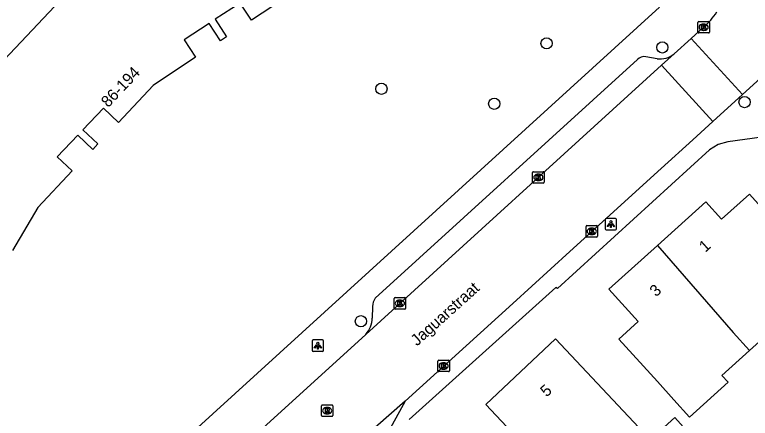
# Model space of a CAD drawing. Extents: x 163150 to 163546, y 380933 to 381635.
# Drawn here: x 163213 to 163277.1, y 381253.2 to 381288.4 of the extents above; entities that cross this region are included whole.
import ezdxf

# ---------------------------------------------------------------- set-up
doc = ezdxf.new("R2010")
doc.units = 0
for name, color, linetype in [('IMGEO_Boom', 7, 'Continuous'), ('IMGEO_Kolk', 7, 'Continuous'), ('IMGEO_Lichtpunt', 7, 'Continuous'), ('IMGEO_Openbare_ruimte_label', 7, 'Continuous'), ('IMGEO_Pand', 7, 'Continuous'), ('IMGEO_Pand_nummerreeks', 7, 'Continuous'), ('IMGEO_Rijbaan_lokaal_open', 7, 'Continuous'), ('IMGEO_Rioolput', 7, 'Continuous'), ('IMGEO_Voetpad_open', 7, 'Continuous')]:
    doc.layers.add(name, color=color, linetype=linetype)

msp = doc.modelspace()

# ---------------------------------------------------------------- linework, layer by layer
at = {"layer": 'IMGEO_Boom'}
for centre in [(163259.341, 381285.869), (163269.438, 381285.511), (163244.945, 381281.901), (163254.778, 381280.597), (163276.605, 381280.745), (163243.161, 381261.625)]:
    msp.add_circle(centre, 0.489, dxfattribs=at)
at = {"layer": 'IMGEO_Kolk'}
for p, q in [((163272.537, 381286.848), (163272.537, 381287.7)), ((163272.612, 381287.774), (163273.464, 381287.774)), ((163273.025, 381287.554), (163273.05, 381287.554)), ((163273.538, 381287.7), (163273.538, 381286.848)), ((163273.048, 381286.994), (163273.023, 381286.994)), ((163273.464, 381286.774), (163272.612, 381286.774)), ((163258.203, 381274.673), (163259.055, 381274.673)), ((163258.128, 381273.747), (163258.128, 381274.599)), ((163258.616, 381274.453), (163258.641, 381274.453)), ((163259.129, 381274.599), (163259.129, 381273.747)), ((163259.055, 381273.673), (163258.203, 381273.673)), ((163258.639, 381273.893), (163258.614, 381273.893)), ((163262.784, 381269.041), (163262.784, 381269.893)), ((163262.859, 381269.967), (163263.711, 381269.967)), ((163263.272, 381269.747), (163263.297, 381269.747)), ((163263.785, 381269.893), (163263.785, 381269.041)), ((163263.711, 381268.967), (163262.859, 381268.967)), ((163263.295, 381269.187), (163263.27, 381269.187)), ((163246.059, 381262.764), (163246.059, 381263.616)), ((163246.134, 381263.69), (163246.986, 381263.69)), ((163246.547, 381263.47), (163246.572, 381263.47)), ((163247.06, 381263.616), (163247.06, 381262.764)), ((163246.986, 381262.69), (163246.134, 381262.69)), ((163246.57, 381262.91), (163246.545, 381262.91)), ((163249.871, 381257.302), (163249.871, 381258.154)), ((163249.946, 381258.228), (163250.798, 381258.228)), ((163250.359, 381258.008), (163250.384, 381258.008)), ((163250.872, 381258.154), (163250.872, 381257.302)), ((163250.382, 381257.448), (163250.357, 381257.448)), ((163250.798, 381257.228), (163249.946, 381257.228))]:
    msp.add_line(p, q, dxfattribs=at)
for points in [[(163272.537, 381286.848), (163272.537, 381287.7)], [(163272.612, 381287.774), (163273.464, 381287.774)], [(163273.538, 381287.7), (163273.538, 381286.848)], [(163272.858, 381287.474), (163272.981, 381287.474), (163272.981, 381287.323), (163273.111, 381287.474), (163273.275, 381287.474), (163273.129, 381287.323), (163273.282, 381287.074), (163273.13, 381287.074), (163273.045, 381287.238), (163272.981, 381287.171), (163272.981, 381287.074), (163272.858, 381287.074), (163272.858, 381287.474)], [(163273.464, 381286.774), (163272.612, 381286.774)], [(163258.203, 381274.673), (163259.055, 381274.673)], [(163258.128, 381273.747), (163258.128, 381274.599)], [(163258.449, 381274.373), (163258.572, 381274.373), (163258.572, 381274.222), (163258.702, 381274.373), (163258.866, 381274.373), (163258.72, 381274.222), (163258.873, 381273.973), (163258.721, 381273.973), (163258.636, 381274.137), (163258.572, 381274.07), (163258.572, 381273.973), (163258.449, 381273.973), (163258.449, 381274.373)], [(163259.129, 381274.599), (163259.129, 381273.747)], [(163259.055, 381273.673), (163258.203, 381273.673)], [(163262.784, 381269.041), (163262.784, 381269.893)], [(163262.859, 381269.967), (163263.711, 381269.967)], [(163263.105, 381269.667), (163263.228, 381269.667), (163263.228, 381269.516), (163263.358, 381269.667), (163263.522, 381269.667), (163263.376, 381269.516), (163263.529, 381269.267), (163263.377, 381269.267), (163263.292, 381269.431), (163263.228, 381269.364), (163263.228, 381269.267), (163263.105, 381269.267), (163263.105, 381269.667)], [(163263.785, 381269.893), (163263.785, 381269.041)], [(163263.711, 381268.967), (163262.859, 381268.967)], [(163246.059, 381262.764), (163246.059, 381263.616)], [(163246.134, 381263.69), (163246.986, 381263.69)], [(163246.38, 381263.39), (163246.503, 381263.39), (163246.503, 381263.239), (163246.633, 381263.39), (163246.797, 381263.39), (163246.651, 381263.239), (163246.804, 381262.99), (163246.652, 381262.99), (163246.567, 381263.154), (163246.503, 381263.087), (163246.503, 381262.99), (163246.38, 381262.99), (163246.38, 381263.39)], [(163247.06, 381263.616), (163247.06, 381262.764)], [(163246.986, 381262.69), (163246.134, 381262.69)], [(163249.871, 381257.302), (163249.871, 381258.154)], [(163249.946, 381258.228), (163250.798, 381258.228)], [(163250.872, 381258.154), (163250.872, 381257.302)], [(163250.192, 381257.928), (163250.315, 381257.928), (163250.315, 381257.777), (163250.445, 381257.928), (163250.609, 381257.928), (163250.463, 381257.777), (163250.616, 381257.528), (163250.464, 381257.528), (163250.379, 381257.692), (163250.315, 381257.625), (163250.315, 381257.528), (163250.192, 381257.528), (163250.192, 381257.928)], [(163250.798, 381257.228), (163249.946, 381257.228)]]:
    msp.add_lwpolyline(points, dxfattribs=at)
for centre, start, end in [((163272.614, 381287.698), 91.55205, 178.44795), ((163272.614, 381287.698), 91.55205, 178.44795), ((163273.462, 381287.698), 1.55205, 88.44795), ((163273.462, 381287.698), 1.55205, 88.44795), ((163272.614, 381286.85), 181.55205, 268.44795), ((163272.614, 381286.85), 181.55205, 268.44795), ((163273.462, 381286.85), 271.55205, 358.44795), ((163273.462, 381286.85), 271.55205, 358.44795), ((163258.205, 381274.597), 91.55205, 178.44795), ((163258.205, 381274.597), 91.55205, 178.44795), ((163259.053, 381274.597), 1.55205, 88.44795), ((163259.053, 381274.597), 1.55205, 88.44795), ((163258.205, 381273.749), 181.55205, 268.44795), ((163258.205, 381273.749), 181.55205, 268.44795), ((163259.053, 381273.749), 271.55205, 358.44795), ((163259.053, 381273.749), 271.55205, 358.44795), ((163262.861, 381269.891), 91.55205, 178.44795), ((163262.861, 381269.891), 91.55205, 178.44795), ((163263.709, 381269.891), 1.55205, 88.44795), ((163263.709, 381269.891), 1.55205, 88.44795), ((163262.861, 381269.043), 181.55205, 268.44795), ((163262.861, 381269.043), 181.55205, 268.44795), ((163263.709, 381269.043), 271.55205, 358.44795), ((163263.709, 381269.043), 271.55205, 358.44795), ((163246.136, 381263.614), 91.55205, 178.44795), ((163246.136, 381263.614), 91.55205, 178.44795), ((163246.984, 381263.614), 1.55205, 88.44795), ((163246.984, 381263.614), 1.55205, 88.44795), ((163246.136, 381262.766), 181.55205, 268.44795), ((163246.136, 381262.766), 181.55205, 268.44795), ((163246.984, 381262.766), 271.55205, 358.44795), ((163246.984, 381262.766), 271.55205, 358.44795), ((163249.948, 381258.152), 91.55205, 178.44795), ((163249.948, 381258.152), 91.55205, 178.44795), ((163250.796, 381258.152), 1.55205, 88.44795), ((163250.796, 381258.152), 1.55205, 88.44795), ((163249.948, 381257.304), 181.55205, 268.44795), ((163249.948, 381257.304), 181.55205, 268.44795), ((163250.796, 381257.304), 271.55205, 358.44795), ((163250.796, 381257.304), 271.55205, 358.44795)]:
    msp.add_arc(centre, 0.0765, start, end, dxfattribs=at)
for centre, major_axis, ratio, start_param, end_param in [((163273.024, 381287.274), (-0.387, 0.002), 0.722429, 4.712389, 7.853982), ((163273.049, 381287.274), (-0.39, 0.002), 0.717154, 1.570796, 4.712389), ((163258.615, 381274.173), (-0.387, 0.002), 0.722429, 4.712389, 7.853982), ((163258.64, 381274.173), (-0.39, 0.002), 0.717154, 1.570796, 4.712389), ((163263.271, 381269.467), (-0.387, 0.002), 0.722429, 4.712389, 7.853982), ((163263.296, 381269.467), (-0.39, 0.002), 0.717154, 1.570796, 4.712389), ((163246.546, 381263.19), (-0.387, 0.002), 0.722429, 4.712389, 7.853982), ((163246.571, 381263.19), (-0.39, 0.002), 0.717154, 1.570796, 4.712389), ((163250.358, 381257.728), (-0.387, 0.002), 0.722429, 4.712389, 7.853982), ((163250.383, 381257.728), (-0.39, 0.002), 0.717154, 1.570796, 4.712389)]:
    msp.add_ellipse(centre, major_axis=major_axis, ratio=ratio, start_param=start_param, end_param=end_param, dxfattribs=at)
at = {"layer": 'IMGEO_Lichtpunt'}
for p, q in [((163264.452, 381270.502), (163264.452, 381269.695)), ((163264.452, 381270.502), (163264.452, 381269.695)), ((163265.354, 381270.597), (163264.546, 381270.597)), ((163265.354, 381270.597), (163264.546, 381270.597)), ((163265.448, 381269.695), (163265.448, 381270.502)), ((163265.448, 381269.695), (163265.448, 381270.502)), ((163264.546, 381269.601), (163265.354, 381269.601)), ((163264.546, 381269.601), (163265.354, 381269.601)), ((163239.804, 381259.997), (163238.996, 381259.997)), ((163239.804, 381259.997), (163238.996, 381259.997)), ((163238.902, 381259.902), (163238.902, 381259.095)), ((163238.902, 381259.902), (163238.902, 381259.095)), ((163239.898, 381259.095), (163239.898, 381259.902)), ((163239.898, 381259.095), (163239.898, 381259.902)), ((163238.996, 381259.001), (163239.804, 381259.001)), ((163238.996, 381259.001), (163239.804, 381259.001))]:
    msp.add_line(p, q, dxfattribs=at)
for points in [[(163264.826, 381270.166), (163264.865, 381270.138), (163264.677, 381269.876), (163264.639, 381269.903), (163264.826, 381270.166)], [(163264.928, 381270.118), (163264.975, 381270.118), (163264.975, 381269.796), (163264.928, 381269.796), (163264.928, 381270.118)], [(163265.038, 381270.138), (163265.076, 381270.165), (163265.263, 381269.903), (163265.224, 381269.875), (163265.038, 381270.138)], [(163239.276, 381259.566), (163239.315, 381259.538), (163239.127, 381259.276), (163239.089, 381259.303), (163239.276, 381259.566)], [(163239.378, 381259.518), (163239.425, 381259.518), (163239.425, 381259.196), (163239.378, 381259.196), (163239.378, 381259.518)], [(163239.488, 381259.538), (163239.526, 381259.565), (163239.713, 381259.303), (163239.674, 381259.275), (163239.488, 381259.538)]]:
    msp.add_lwpolyline(points, dxfattribs=at)
for centre in [(163264.951, 381270.3), (163239.401, 381259.7)]:
    msp.add_circle(centre, 0.0994, dxfattribs=at)
for centre, start, end in [((163264.546, 381270.502), 90, 180), ((163264.546, 381270.502), 90, 180), ((163265.354, 381270.502), 0, 90), ((163265.354, 381270.502), 0, 90), ((163264.546, 381269.695), 180, 270), ((163264.546, 381269.695), 180, 270), ((163265.354, 381269.695), 270, 0), ((163265.354, 381269.695), 270, 360), ((163238.996, 381259.902), 90, 180), ((163238.996, 381259.902), 90, 180), ((163239.804, 381259.902), 0, 90), ((163239.804, 381259.902), 0, 90), ((163238.996, 381259.095), 180, 270), ((163238.996, 381259.095), 180, 270), ((163239.804, 381259.095), 270, 0), ((163239.804, 381259.095), 270, 360)]:
    msp.add_arc(centre, 0.0946, start, end, dxfattribs=at)
at = {"layer": 'IMGEO_Pand'}
for points in [[(163187.968, 381233.07), (163193.271, 381250), (163197.467, 381263.396), (163206.151, 381278.206), (163217.937, 381290.687), (163232.209, 381300.168), (163248.202, 381306.183), (163251.969, 381306.664), (163251.737, 381308.49), (163248.676, 381308.083), (163248.28, 381310.782), (163251.461, 381311.208), (163254.337, 381311.635), (163256.45, 381311.907)], [(163237.243, 381290.295), (163233.616, 381287.89), (163232.621, 381289.384), (163230.464, 381287.988), (163231.434, 381286.446), (163230.917, 381286.089), (163229.925, 381287.599), (163227.746, 381286.177), (163228.737, 381284.659), (163225.055, 381282.196), (163222.016, 381278.976), (163220.707, 381280.212), (163218.918, 381278.33), (163220.215, 381277.093), (163219.787, 381276.62), (163218.477, 381277.865), (163216.681, 381275.981), (163217.981, 381274.734), (163214.984, 381271.543), (163212.779, 381267.801)], [(163269.002, 381268.232), (163273.224, 381272.045), (163274.601, 381270.52), (163277.026, 381272.71), (163280.377, 381268.999), (163281.39, 381267.876), (163280.896, 381267.43), (163283.318, 381264.748), (163279.109, 381260.944), (163277.04, 381259.074)], [(163277.04, 381259.074), (163274.635, 381256.902), (163275.172, 381256.308), (163271.803, 381253.264), (163270.439, 381254.773), (163269.004, 381256.361), (163265.652, 381260.071), (163267.336, 381261.592), (163264.781, 381264.419), (163269.002, 381268.232)], [(163269.002, 381268.232), (163275.617, 381260.65), (163277.04, 381259.074)], [(163270.859, 381233.088), (163266.522, 381237.793), (163270.892, 381241.794), (163264.13, 381249.279), (163261.324, 381246.64), (163254.056, 381254.37), (163260.133, 381260.084), (163267.4, 381252.354), (163267.219, 381252.189), (163267.042, 381252.027), (163267.537, 381251.485), (163268.019, 381250.956), (163270.516, 381253.234), (163278.474, 381244.372)]]:
    msp.add_lwpolyline(points, dxfattribs=at)
at = {"layer": 'IMGEO_Rijbaan_lokaal_open'}
for points in [[(163273.039, 381287.273), (163271.964, 381286.302)], [(163271.964, 381286.302), (163270.465, 381284.947)], [(163271.964, 381286.302), (163276.429, 381281.397)], [(163276.429, 381281.397), (163281.482, 381285.994), (163281.963, 381286.424)], [(163269.371, 381283.951), (163270.465, 381284.947)], [(163269.371, 381283.951), (163243.582, 381260.479)], [(163273.84, 381279.042), (163269.371, 381283.951)], [(163276.429, 381281.397), (163273.84, 381279.042)], [(163273.84, 381279.042), (163272.106, 381277.464), (163269.336, 381274.944), (163261.385, 381267.72), (163256.395, 381263.184), (163247.004, 381254.649)], [(163243.582, 381260.479), (163233.963, 381251.702)], [(163247.004, 381254.649), (163239.4, 381247.963), (163238.786, 381247.234)], [(163247.004, 381254.649), (163245.557, 381252)]]:
    msp.add_lwpolyline(points, dxfattribs=at)
msp.add_arc((163268.306, 381292.501), 7.052, 312.15379, 326.47392, dxfattribs=at)
at = {"layer": 'IMGEO_Rioolput'}
for p, q in [((163239.715, 381253.393), (163239.715, 381254.245)), ((163239.79, 381254.319), (163240.642, 381254.319)), ((163240.716, 381254.245), (163240.716, 381253.393)), ((163240.226, 381253.539), (163240.201, 381253.539)), ((163240.203, 381254.099), (163240.228, 381254.099)), ((163240.642, 381253.319), (163239.79, 381253.319))]:
    msp.add_line(p, q, dxfattribs=at)
for points in [[(163239.715, 381253.393), (163239.715, 381254.245)], [(163239.79, 381254.319), (163240.642, 381254.319)], [(163240.716, 381254.245), (163240.716, 381253.393)], [(163240.304, 381254.017), (163240.052, 381254.019), (163240.052, 381253.619)], [(163240.052, 381253.619), (163240.176, 381253.619), (163240.176, 381253.781), (163240.187, 381253.781)], [(163240.23, 381253.938), (163240.176, 381253.938), (163240.176, 381253.857)], [(163240.176, 381253.857), (163240.228, 381253.857)], [(163240.234, 381253.752), (163240.305, 381253.619), (163240.445, 381253.619), (163240.38, 381253.745)], [(163240.642, 381253.319), (163239.79, 381253.319)]]:
    msp.add_lwpolyline(points, dxfattribs=at)
for centre, radius, start, end in [((163239.792, 381254.243), 0.0765, 91.55205, 178.44795), ((163239.792, 381254.243), 0.0765, 91.55205, 178.44795), ((163240.64, 381254.243), 0.0765, 1.55205, 88.44795), ((163240.64, 381254.243), 0.0765, 1.55205, 88.44795), ((163240.186, 381253.728), 0.0533, 26.02933, 88.69889), ((163240.212, 381254.046), 0.19, 274.7715, 282.96867), ((163240.236, 381253.842), 0.0964, 77.00612, 93.18647), ((163240.25, 381253.899), 0.0378, 276.66336, 79.67722), ((163240.303, 381253.907), 0.109, 350.36119, 89.41601), ((163240.301, 381253.907), 0.112, 277.58423, 350.98172), ((163240.285, 381253.692), 0.108, 29.51342, 73.79051), ((163239.792, 381253.395), 0.0765, 181.55205, 268.44795), ((163239.792, 381253.395), 0.0765, 181.55205, 268.44795), ((163240.64, 381253.395), 0.0765, 271.55205, 358.44795), ((163240.64, 381253.395), 0.0765, 271.55205, 358.44795)]:
    msp.add_arc(centre, radius, start, end, dxfattribs=at)
for centre, major_axis, ratio, start_param, end_param in [((163240.202, 381253.819), (-0.387, 0.002), 0.722429, 4.712389, 7.853982), ((163240.227, 381253.819), (-0.39, 0.002), 0.717154, 1.570796, 4.712389)]:
    msp.add_ellipse(centre, major_axis=major_axis, ratio=ratio, start_param=start_param, end_param=end_param, dxfattribs=at)
at = {"layer": 'IMGEO_Voetpad_open'}
for points in [[(163198.814, 381224.874), (163226.368, 381250), (163269.177, 381289.036), (163267.999, 381290.328), (163270.661, 381292.68)], [(163267.264, 381284.445), (163244.41, 381263.628)], [(163268.976, 381284.517), (163267.993, 381284.687)], [(163286.554, 381278.836), (163284.028, 381278.488), (163275.144, 381277.265), (163274.301, 381277.041), (163273.554, 381276.589), (163260.303, 381264.494), (163260.154, 381264.566), (163247.371, 381253.054)], [(163244.164, 381262.916), (163244.138, 381261.908)]]:
    msp.add_lwpolyline(points, dxfattribs=at)
for centre, radius, start, end in [((163269.223, 381286.455), 1.953, 262.73317, 309.48261), ((163267.809, 381284.022), 0.69, 74.52029, 142.20808), ((163245.458, 381262.867), 1.295, 144.03439, 177.84497), ((163242.049, 381261.898), 2.089, 317.20768, 0.27196)]:
    msp.add_arc(centre, radius, start, end, dxfattribs=at)

# ---------------------------------------------------------------- texts
at = {"layer": 'IMGEO_Openbare_ruimte_label'}
msp.add_text('Jaguarstraat', height=1, rotation=41.99999, dxfattribs=at).set_placement((163248.05, 381259.416))
at = {"layer": 'IMGEO_Pand_nummerreeks'}
for s, rotation, p in [('86-194', 46.65595, (163221.125, 381280.217)), ('1', 42.08948, (163273.192, 381267.596)), ('3', 42.0894, (163268.886, 381263.707)), ('5', 41.9463, (163259.346, 381254.969))]:
    msp.add_text(s, height=1, rotation=rotation, dxfattribs=at).set_placement(p)

doc.saveas('drawing.dxf')
